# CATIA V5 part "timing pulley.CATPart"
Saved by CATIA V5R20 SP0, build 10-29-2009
Part number: timing pulley
Source: Unknown
Bounding box of the stored display mesh (mm): x -7.481 to 7.481, y 0.019 to 14.981, z 0 to 15
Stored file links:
  C:\Users\Ikarus\OneDrive - FH JOANNEUM\BAC - Arbeit 1\CAD Modell\CAD-Modell-Step files\Platzhalter\timing pulley.CATPart
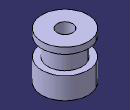
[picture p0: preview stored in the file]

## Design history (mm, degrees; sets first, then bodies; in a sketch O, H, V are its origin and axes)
Body1 (main body)
  Solid1 "Hauptkörper": solid without history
